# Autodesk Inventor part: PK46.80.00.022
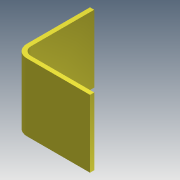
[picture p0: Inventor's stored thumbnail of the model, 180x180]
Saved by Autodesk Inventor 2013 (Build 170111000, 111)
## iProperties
Created: 2005-04
Part Number: PK46.80.00.022
Material: Steel, Mild
Document SubType Name: Sheet Metal
Designer: salex
Manufacturer: Standard
Standards Organization: Custom
Density: 7.86 g/cm^3
Sheet Metal Rule: Default
Mass: 4266.66 g
Surface Area: 1185.52 cm^2
Volume: 542.832 cm^3
Author: salex
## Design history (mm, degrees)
node "ФлнОтгиб1"
body "Solid1"
sketch "Эскиз1"
  geometry: L1 (0, 0)-(0, 170); L2 (0, 0)-(170, 0)
  constraints: 4 end point, 1 perpendicular, 1 vertical, 1 other
  dimensions: "d0" = 170 distance of L1.start L2.end; "d1" = 170 distance of L1.start L1.end (= d0)
feature "Плакирование1" dims "d2" = 160, "d3" = 10 (= BendReliefWidth), "d5" = 20 (= MinimumRemnant), "d7" = 20 (= BendRadius), "d8" = 10, "Thickness" = 10
feature "Изгиб1" dims "d3" = 10 (= BendReliefWidth), "d4" = 5 (= BendReliefDepth), "d5" = 20 (= MinimumRemnant), "d6" = 20 (= BendRadius), "d7" = 20 (= BendRadius), "d8" = 10, "SeamGap" = 0.01, "Thickness" = 10
other parameters: "BendRadius" = 20, "BendReliefDepth" = 5 (= 0.5 x Thickness)
